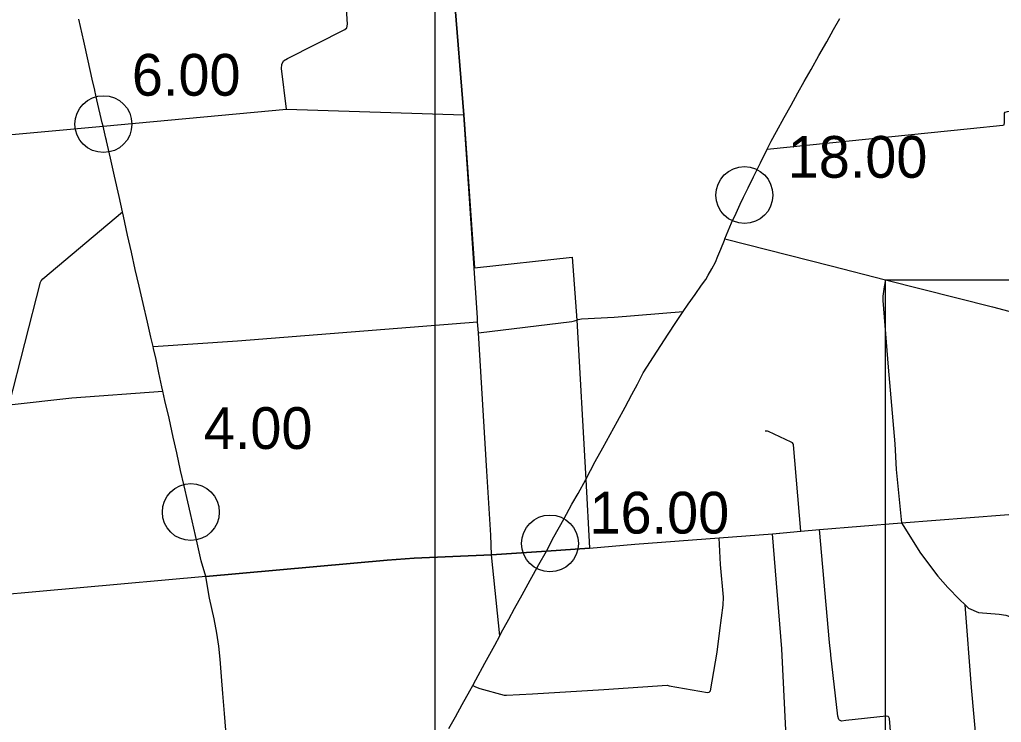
# Model space of a CAD drawing. Extents: x 1659811 to 1934326, y 644115 to 934867.
# Drawn here: x 1718647 to 1744520, y 830360 to 848887 of the extents above; entities that cross this region are included whole.
import ezdxf

# ---------------------------------------------------------------- set-up
doc = ezdxf.new("R2010")
doc.units = 0
for name, color, linetype in [('Default', 7, 'Continuous'), ('GM_X_County_Road', 7, 'Continuous'), ('GM_X_State_Route', 7, 'Continuous'), ('GM_X_Township', 7, 'Continuous'), ('GM_X_Township_Road', 7, 'Continuous'), ('SC_Scratch1', 7, 'Continuous'), ('SH_Text', 7, 'Continuous')]:
    doc.layers.add(name, color=color, linetype=linetype)

msp = doc.modelspace()

# ---------------------------------------------------------------- linework, layer by layer
at = {"layer": 'Default'}
for centre in [(1720856, 846132), (1737748, 844261), (1723158, 835904), (1732623, 835077)]:
    msp.add_circle(centre, 750, dxfattribs=at)
at = {"layer": 'GM_X_County_Road'}
for points in [[(1731084, 834778), (1731084, 834778), (1731061, 835293), (1730956, 836981), (1730741, 840627), (1730718, 840920), (1730710, 841024), (1730491, 844303), (1730357, 846374), (1730103, 849536)], [(1738347, 845475), (1743708, 846017), (1744558, 846102), (1744590, 846116), (1744600, 846172), (1744604, 846421), (1744622, 846447), (1744680, 846465), (1745876, 846572)], [(1720847, 846076), (1725683, 846525), (1730357, 846374)], [(1708801, 844432), (1708902, 844482), (1709008, 844522), (1709725, 844656), (1710340, 844759), (1714204, 845470), (1720847, 846076)], [(1716724, 834166), (1716768, 834259), (1716837, 834440), (1716964, 834825), (1717845, 836509), (1717938, 836716), (1718374, 838728), (1718375, 838734), (1719193, 841964), (1719213, 842004), (1719259, 842057), (1721361, 843817)], [(1737234, 843108), (1740034, 842392), (1741462, 842026), (1744288, 841317), (1746468, 840732), (1746689, 840660), (1746799, 840615)], [(1741462, 842026), (1741435, 841844), (1741393, 841597), (1741392, 841485), (1741537, 839722), (1741708, 837701), (1741749, 837030), (1741888, 835621)], [(1733272, 840949), (1733333, 840968), (1733366, 840980), (1733453, 840996), (1734313, 841045), (1736130, 841189)], [(1730741, 840627), (1733198, 840926), (1733272, 840949)], [(1738495, 835335), (1739233, 835399), (1739729, 835443), (1741888, 835621)], [(1741888, 835621), (1741888, 835621), (1741929, 835550), (1742391, 834821), (1742843, 834211), (1743107, 833912), (1743416, 833603), (1743565, 833455), (1743653, 833369), (1743918, 833260), (1744460, 833210), (1744636, 833182), (1745155, 832998), (1745425, 832893), (1745591, 832848), (1745853, 832842)], [(1732535, 834878), (1733669, 834953), (1734863, 835055), (1737084, 835225), (1738492, 835335), (1738495, 835335)], [(1723553, 834208), (1728329, 834640), (1729048, 834685), (1731084, 834778), (1732535, 834878)], [(1731299, 832638), (1731084, 834778)], [(1744167, 826399), (1743941, 828936), (1743731, 831276), (1743565, 833455)]]:
    msp.add_lwpolyline(points, dxfattribs=at)
at = {"layer": 'GM_X_State_Route'}
for points in [[(1720626, 847027), (1720561, 847316), (1720450, 847801), (1720335, 848320), (1720209, 848899)], [(1729959, 830195), (1730130, 830505), (1730307, 830831), (1730516, 831194), (1730587, 831329), (1730669, 831484), (1730905, 831922), (1731168, 832392), (1731299, 832638), (1731341, 832718), (1731537, 833078), (1731691, 833362), (1731893, 833720), (1732106, 834111), (1732327, 834521), (1732535, 834878), (1732728, 835252), (1732987, 835719), (1733197, 836111), (1733363, 836397), (1733565, 836759), (1733817, 837237), (1734015, 837601), (1734208, 837949), (1734401, 838301), (1734605, 838671), (1734780, 839005), (1734928, 839279), (1735030, 839470), (1735084, 839573), (1735178, 839728), (1735348, 839994), (1735541, 840296), (1735735, 840596), (1735940, 840905), (1736130, 841189), (1736269, 841383), (1736449, 841643), (1736620, 841887), (1736730, 842034), (1736794, 842147), (1736886, 842314), (1736983, 842497), (1737049, 842648), (1737126, 842838), (1737220, 843073), (1737234, 843108), (1737317, 843316), (1737408, 843527), (1737530, 843788), (1737633, 844018), (1737720, 844206), (1737844, 844452), (1737988, 844743), (1738169, 845113), (1738347, 845475), (1738450, 845686), (1738590, 845936), (1738795, 846310), (1738976, 846634), (1739159, 846957), (1739325, 847256), (1739504, 847572), (1739709, 847941), (1739919, 848303), (1740096, 848623), (1740266, 848921)], [(1720934, 845700), (1720919, 845766), (1720847, 846076), (1720826, 846163), (1720682, 846776), (1720627, 847021), (1720626, 847027)], [(1723553, 834208), (1723432, 834618), (1723330, 835095), (1723239, 835484), (1723150, 835869), (1723079, 836177), (1722984, 836598), (1722891, 836997), (1722788, 837464), (1722693, 837882), (1722586, 838377), (1722478, 838842), (1722420, 839096), (1722394, 839209), (1722315, 839576), (1722242, 839929), (1722179, 840219), (1722165, 840273), (1722106, 840514), (1722013, 840911), (1721900, 841406), (1721795, 841863), (1721692, 842302), (1721591, 842759), (1721490, 843204), (1721387, 843703), (1721361, 843817), (1721268, 844221), (1721145, 844756), (1721038, 845239), (1720935, 845695), (1720934, 845700)], [(1724141, 829440), (1724118, 829683), (1724082, 830151), (1724047, 830596), (1724004, 831121), (1723970, 831565), (1723933, 832026), (1723894, 832366), (1723847, 832711), (1723776, 833089), (1723654, 833634), (1723553, 834208)]]:
    msp.add_lwpolyline(points, dxfattribs=at)
at = {"layer": 'GM_X_Township'}
for points in [[(1730103, 849536), (1730357, 846374), (1730639, 842341), (1733208, 842623), (1733333, 840968), (1733565, 836759), (1733669, 834953), (1732535, 834878), (1731084, 834778), (1729048, 834685), (1728329, 834640), (1723553, 834208), (1716919, 833606)], [(1741445, 808665), (1740683, 814235), (1740027, 819303), (1739320, 826121), (1739190, 826110), (1738896, 829083), (1738732, 832296), (1738492, 835335), (1739233, 835399), (1739729, 835443), (1741888, 835621), (1745504, 835902), (1745235, 839100), (1746371, 839211), (1748425, 839454), (1750554, 839662), (1752575, 839860), (1752247, 843701), (1755343, 843985), (1758992, 844295), (1759463, 844341)], [(1733669, 834953), (1734863, 835055), (1737084, 835225), (1738492, 835335)]]:
    msp.add_lwpolyline(points, dxfattribs=at)
at = {"layer": 'GM_X_Township_Road'}
for points in [[(1725683, 846525), (1725544, 847597), (1725561, 847705), (1725604, 847799), (1725703, 847865), (1727216, 848627), (1727270, 848673), (1727287, 848765), (1727197, 850146)], [(1722165, 840273), (1724391, 840415), (1730718, 840920)], [(1718374, 838728), (1720021, 838914), (1722420, 839096)], [(1739233, 835399), (1739046, 837680), (1739037, 837707), (1739016, 837727), (1738982, 837743), (1738382, 838032), (1738356, 838040), (1738298, 838036)], [(1740025, 832157), (1739989, 832466), (1739729, 835443)], [(1730587, 831329), (1730657, 831293), (1730779, 831249), (1731415, 831076), (1731477, 831073), (1732165, 831108), (1734040, 831223), (1735708, 831338), (1735762, 831326), (1736778, 831151), (1736820, 831155), (1736850, 831191), (1737028, 832208), (1737103, 832781), (1737184, 833453), (1737194, 833663), (1737122, 834523), (1737084, 835225)], [(1741747, 828267), (1741568, 830460), (1741557, 830498), (1741539, 830517), (1741481, 830521), (1740421, 830411), (1740309, 830396), (1740253, 830420), (1740235, 830434), (1740214, 830523), (1740028, 832129), (1740025, 832157)]]:
    msp.add_lwpolyline(points, dxfattribs=at)
at = {"layer": 'SC_Scratch1'}
msp.add_lwpolyline([(1729596, 899996), (1925846, 899996), (1925846, 765496), (1729596, 765496)], close=True, dxfattribs=at)
at = {"layer": 'SH_Text'}
msp.add_lwpolyline([(1741462, 842026), (1846073, 842026), (1846073, 754070), (1741462, 754070)], close=True, dxfattribs=at)

# ---------------------------------------------------------------- texts
at = {"layer": 'Default'}
for s, p in [('6.00', (1721606, 846882)), ('18.00', (1738889, 844718)), ('4.00', (1723501, 837569)), ('16.00', (1733666, 835338))]:
    msp.add_text(s, height=1100, dxfattribs=at).set_placement(p)

doc.saveas('drawing.dxf')
